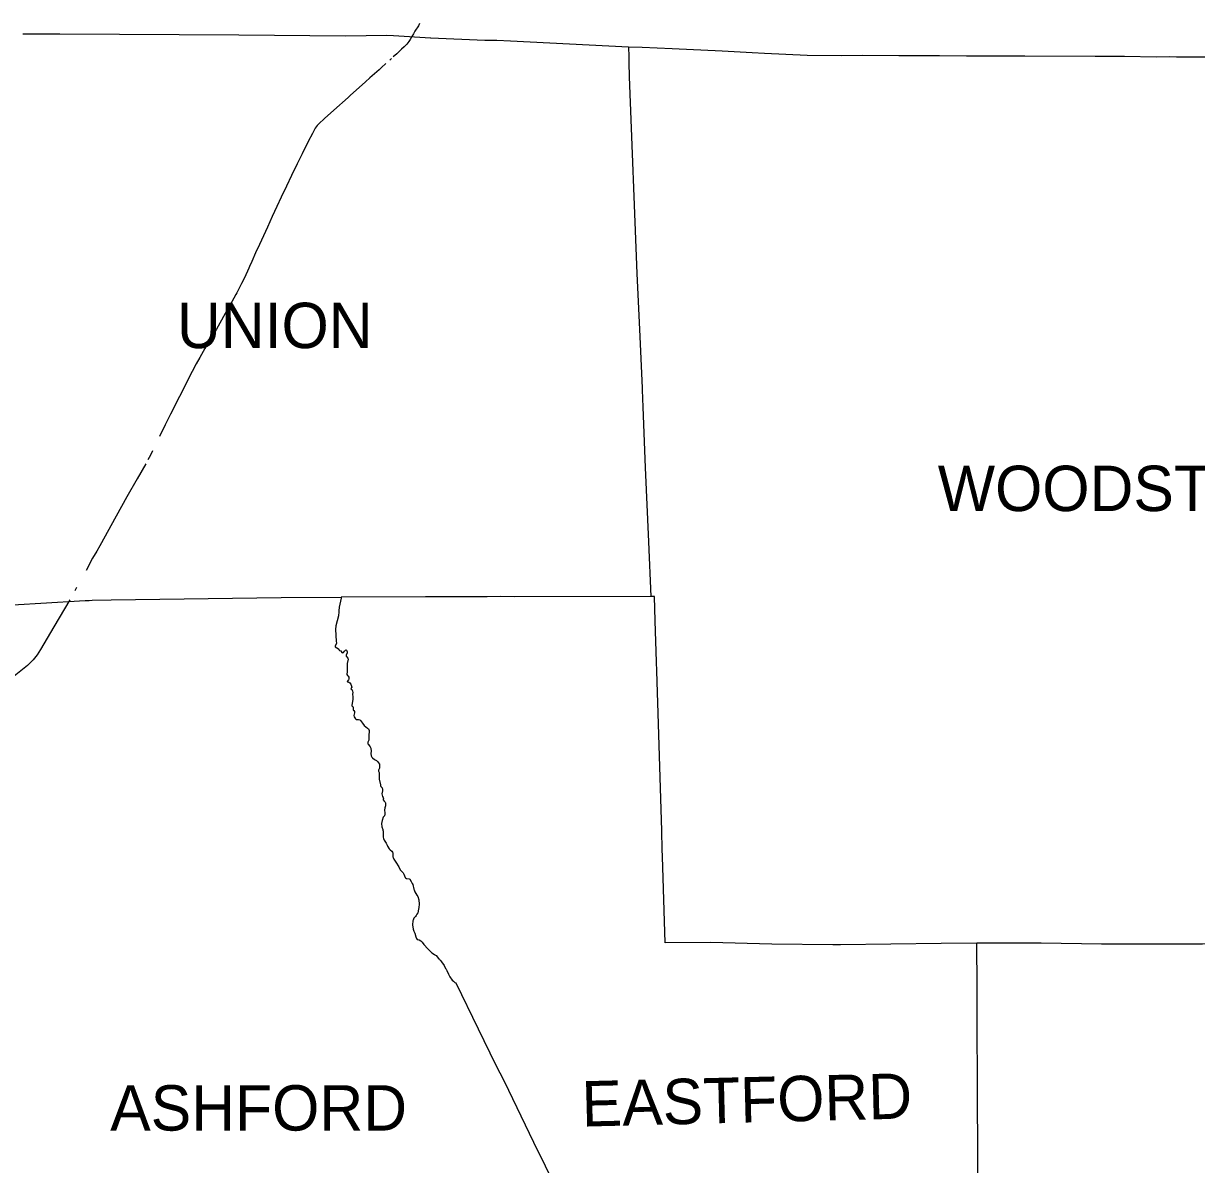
# Model space of a CAD drawing. Extents: x 0 to 2603, y -226 to 830.
# Drawn here: x 287.25 to 322.13, y 668.33 to 702.26 of the extents above; entities that cross this region are included whole.
import ezdxf

# ---------------------------------------------------------------- set-up
doc = ezdxf.new("R2010")
doc.units = 0
for name, color, linetype in [('CT_TSH_Map_Districts', 7, 'Continuous'), ('CT_TSH_Map_Interstate_Roads', 7, 'Continuous'), ('CT_TSH_Map_Town_Limits', 7, 'Continuous'), ('CT_TSH_Map_Town_Text', 7, 'Continuous')]:
    doc.layers.add(name, color=color, linetype=linetype)

msp = doc.modelspace()

# ---------------------------------------------------------------- linework, layer by layer
at = {"layer": 'CT_TSH_Map_Districts'}
for points in [[(305.24, 701.567), (305.249, 701.267), (305.252, 701.1), (305.265, 700.678), (305.492, 694.828)], [(305.492, 694.828), (305.567, 693.161), (305.644, 691.422), (305.646, 691.368), (305.665, 690.852), (305.738, 689.061), (305.834, 686.851), (305.903, 685.224)], [(285.263, 684.866), (285.933, 684.911), (287.104, 684.983), (287.764, 685.023), (289.085, 685.105), (289.205, 685.102), (289.289, 685.108), (289.862, 685.118), (294.917, 685.193), (296.698, 685.197)], [(305.903, 685.224), (301.859, 685.207), (301.443, 685.218), (301.039, 685.215), (299.208, 685.211), (296.698, 685.197)]]:
    msp.add_lwpolyline(points, dxfattribs=at)
at = {"layer": 'CT_TSH_Map_Interstate_Roads'}
for points in [[(299.029, 702.262), (298.991, 702.196), (298.89, 702.034), (298.843, 701.957), (298.798, 701.877), (298.749, 701.784), (298.711, 701.729)], [(298.711, 701.729), (298.675, 701.681), (298.645, 701.647), (298.611, 701.61), (298.569, 701.568), (298.495, 701.494), (298.352, 701.36), (298.245, 701.265)], [(298.193, 701.221), (298.141, 701.17)], [(297.823, 700.884), (297.551, 700.643)], [(297.895, 700.948), (297.823, 700.884)], [(298.027, 701.068), (297.895, 700.948)], [(297.418, 700.523), (296.961, 700.116)], [(297.551, 700.643), (297.418, 700.523)], [(296.961, 700.116), (296.901, 700.062), (296.479, 699.684)], [(296.479, 699.684), (296.201, 699.436), (296.037, 699.282), (295.986, 699.226), (295.95, 699.183), (295.924, 699.145), (295.892, 699.092), (295.839, 698.993), (295.719, 698.747), (295.534, 698.381), (295.39, 698.09), (295.222, 697.744), (295.07, 697.428), (294.913, 697.097), (294.782, 696.814), (294.648, 696.526), (294.502, 696.209), (294.385, 695.951), (294.265, 695.687), (294.151, 695.436), (294.039, 695.187)], [(294.039, 695.187), (293.973, 695.039), (293.946, 694.98), (293.819, 694.699), (293.737, 694.526), (293.668, 694.387), (293.595, 694.249), (293.569, 694.2), (293.447, 693.984), (293.309, 693.744), (293.136, 693.435), (292.986, 693.172), (292.92, 693.057), (292.84, 692.925), (292.7, 692.696), (292.643, 692.6), (292.539, 692.418)], [(292.539, 692.418), (292.489, 692.33), (292.383, 692.136), (292.264, 691.91), (291.887, 691.17), (291.623, 690.645), (291.465, 690.323), (291.294, 689.98)], [(291.087, 689.553), (291.078, 689.524), (290.986, 689.357), (290.948, 689.282)], [(290.886, 689.168), (290.627, 688.719), (290.323, 688.18), (290.01, 687.612), (289.523, 686.729), (289.43, 686.568), (289.302, 686.363)], [(289.302, 686.363), (289.118, 685.995)], [(288.827, 685.488), (288.775, 685.394)], [(288.632, 685.126), (288.156, 684.322), (287.757, 683.642), (287.653, 683.489), (287.537, 683.342), (287.478, 683.275), (287.37, 683.171), (287.172, 683.014), (287.023, 682.893), (286.838, 682.761), (286.581, 682.61), (286.2, 682.399)]]:
    msp.add_lwpolyline(points, dxfattribs=at)
at = {"layer": 'CT_TSH_Map_Town_Limits'}
for points in [[(287.227, 701.95), (288.33, 701.956), (293.654, 701.922), (296.827, 701.891), (298.059, 701.91), (298.257, 701.902), (299.351, 701.838), (299.357, 701.838), (299.361, 701.837), (300.965, 701.762), (301.321, 701.764), (301.732, 701.741), (305.24, 701.567)], [(305.24, 701.567), (305.642, 701.557), (305.648, 701.556), (306.535, 701.513), (308.024, 701.446), (308.92, 701.402), (309.28, 701.383), (310.551, 701.318), (311.572, 701.314), (312.203, 701.315), (313.281, 701.309), (314.492, 701.307), (315.289, 701.301), (316.497, 701.299), (317.024, 701.304), (319.113, 701.292), (319.993, 701.288), (320.928, 701.272), (321.329, 701.277), (321.539, 701.265), (322.379, 701.272)], [(305.24, 701.567), (305.249, 701.267), (305.252, 701.1), (305.265, 700.678), (305.492, 694.828)], [(305.492, 694.828), (305.567, 693.161), (305.644, 691.422), (305.646, 691.368), (305.665, 690.852), (305.738, 689.061), (305.834, 686.851), (305.903, 685.224)], [(285.263, 684.866), (285.933, 684.911), (287.104, 684.983), (287.764, 685.023), (289.085, 685.105), (289.205, 685.102), (289.289, 685.108), (289.862, 685.118), (294.917, 685.193), (296.698, 685.197)], [(296.698, 685.197), (296.696, 685.175), (296.638, 684.904), (296.624, 684.796), (296.625, 684.764), (296.62, 684.644), (296.535, 684.351), (296.523, 684.236), (296.552, 683.895), (296.553, 683.829), (296.513, 683.739), (296.517, 683.727), (296.613, 683.666), (296.627, 683.653), (296.633, 683.629), (296.651, 683.619), (296.691, 683.61), (296.714, 683.551), (296.741, 683.546), (296.764, 683.554), (296.791, 683.591), (296.836, 683.631), (296.854, 683.628), (296.864, 683.607), (296.872, 683.58), (296.871, 683.547), (296.846, 683.472), (296.846, 683.447), (296.899, 683.386), (296.902, 683.355), (296.871, 683.231), (296.87, 683.126), (296.87, 682.994), (296.866, 682.899), (296.882, 682.872), (296.908, 682.853), (296.924, 682.822), (296.928, 682.782), (296.925, 682.76), (296.912, 682.74), (296.872, 682.696), (296.882, 682.682), (296.928, 682.673), (296.954, 682.655), (296.981, 682.61), (297.012, 682.528), (296.986, 682.482), (296.99, 682.469), (297.021, 682.442), (297.038, 682.408), (297.042, 682.362), (297.035, 682.32), (297.042, 682.241), (297.041, 682.16), (297.014, 681.993), (297.015, 681.972), (297.045, 681.952), (297.053, 681.923), (297.052, 681.849), (297.057, 681.84), (297.073, 681.828), (297.088, 681.797), (297.094, 681.761), (297.075, 681.68), (297.084, 681.643), (297.118, 681.584), (297.14, 681.565), (297.215, 681.565), (297.25, 681.555), (297.274, 681.532), (297.326, 681.458), (297.383, 681.389), (297.482, 681.308), (297.51, 681.287), (297.53, 681.233), (297.529, 681.18), (297.521, 681.125), (297.518, 681.113), (297.523, 680.995), (297.516, 680.951), (297.493, 680.893), (297.492, 680.84), (297.505, 680.816), (297.526, 680.786), (297.557, 680.751), (297.577, 680.712), (297.588, 680.619), (297.579, 680.548), (297.587, 680.484), (297.606, 680.444), (297.629, 680.424), (297.692, 680.371), (297.748, 680.341), (297.781, 680.315), (297.832, 680.237), (297.841, 680.195), (297.832, 680.12), (297.806, 680.059), (297.809, 680.031), (297.826, 679.985), (297.822, 679.901)], [(305.903, 685.224), (301.859, 685.207), (301.443, 685.218), (301.039, 685.215), (299.208, 685.211), (296.698, 685.197)], [(315.602, 674.908), (314.541, 674.9), (311.546, 674.859), (311.316, 674.859), (309.502, 674.879), (307.682, 674.927), (306.33, 674.917), (306.255, 677.487), (306.244, 677.693), (306.233, 678.253), (306.139, 681.121), (306.086, 682.998), (306.075, 683.281), (306.037, 684.496), (306.013, 685.223), (305.903, 685.224)], [(297.822, 679.901), (297.826, 679.792), (297.866, 679.625), (297.866, 679.603), (297.875, 679.571), (297.911, 679.53), (297.926, 679.483), (297.926, 679.437), (297.91, 679.351), (297.917, 679.308), (297.925, 679.278), (297.949, 679.248), (297.951, 679.213), (297.943, 679.189), (297.943, 679.172), (297.973, 679.136), (298.004, 679.1), (298.011, 679.084), (298.018, 679), (297.999, 678.939), (297.985, 678.867), (297.991, 678.789), (297.992, 678.752), (297.981, 678.702), (297.945, 678.655), (297.911, 678.558), (297.893, 678.472), (297.905, 678.371), (297.932, 678.292), (297.935, 678.265), (297.942, 678.249), (297.946, 678.154), (297.944, 678.065), (297.953, 678.024), (297.978, 677.974), (298.031, 677.887), (298.065, 677.828), (298.075, 677.797), (298.125, 677.715), (298.149, 677.687), (298.198, 677.645), (298.225, 677.614), (298.235, 677.588), (298.234, 677.534), (298.234, 677.483), (298.238, 677.461), (298.264, 677.406), (298.322, 677.321), (298.409, 677.181), (298.454, 677.088), (298.498, 677.042), (298.543, 677.003), (298.563, 676.965), (298.599, 676.866), (298.608, 676.853), (298.639, 676.838), (298.715, 676.828), (298.735, 676.817), (298.78, 676.747), (298.802, 676.704), (298.81, 676.683), (298.826, 676.659), (298.862, 676.518), (298.871, 676.496), (298.889, 676.442), (298.949, 676.335), (298.972, 676.295), (299.005, 676.198), (299.015, 676.067), (299.01, 675.97), (298.989, 675.876), (298.982, 675.83), (298.976, 675.812), (298.951, 675.772), (298.93, 675.73), (298.911, 675.702), (298.861, 675.654), (298.847, 675.625), (298.839, 675.598), (298.829, 675.579), (298.813, 675.455), (298.84, 675.325), (298.861, 675.265), (298.887, 675.206), (298.912, 675.097), (298.937, 675.053), (298.957, 675.016), (299.012, 675.007), (299.066, 674.981), (299.105, 674.941), (299.154, 674.871), (299.271, 674.741), (299.394, 674.629), (299.471, 674.571), (299.479, 674.561), (299.519, 674.541), (299.59, 674.459), (299.616, 674.439), (299.629, 674.414), (299.664, 674.385), (299.675, 674.36)], [(334.9, 675.527), (334.314, 675.502), (334.08, 675.488), (332.54, 675.407), (330.718, 675.306), (327.409, 675.146), (326.785, 675.112), (326.12, 675.081), (325.146, 675.021), (323.414, 674.936), (322.312, 674.881), (321.154, 674.886), (319.305, 674.886), (317.509, 674.908), (316.548, 674.913), (315.602, 674.908)], [(315.655, 655.339), (315.654, 655.634), (315.654, 656.102), (315.646, 656.75), (315.643, 658.652), (315.637, 659.544), (315.641, 660.468), (315.642, 660.556), (315.643, 660.89), (315.642, 660.907), (315.639, 661.876), (315.635, 662.736), (315.635, 662.956), (315.631, 664.227), (315.609, 665.598), (315.626, 668.199), (315.617, 670.871), (315.613, 672.33), (315.607, 673.551), (315.608, 674.037), (315.6, 674.481), (315.602, 674.908)], [(299.675, 674.36), (299.762, 674.244), (299.8, 674.155), (299.817, 674.135), (299.835, 674.098), (299.883, 673.99), (299.927, 673.909), (299.999, 673.812), (300.034, 673.778), (300.079, 673.745), (300.106, 673.732), (300.774, 672.366), (301.288, 671.308), (301.544, 670.803), (302.412, 668.994), (302.76, 668.294), (303.801, 666.185), (303.825, 665.494), (303.764, 663.677), (303.599, 659.069), (303.518, 656.741), (303.515, 656.627), (303.487, 655.925), (303.464, 655.31)]]:
    msp.add_lwpolyline(points, dxfattribs=at)

# ---------------------------------------------------------------- texts
at = {"layer": 'CT_TSH_Map_Town_Text'}
for s, p in [('UNION', (291.814, 692.607)), ('WOODSTOCK', (314.437, 687.761)), ('ASHFORD', (289.829, 669.338))]:
    msp.add_text(s, height=1.35, dxfattribs=at).set_placement(p)
msp.add_text('EASTFORD', height=1.35, rotation=1.431, dxfattribs=at).set_placement((303.863, 669.455))

doc.saveas('drawing.dxf')
